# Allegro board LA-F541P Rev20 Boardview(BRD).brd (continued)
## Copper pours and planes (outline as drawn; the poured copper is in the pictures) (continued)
BST1_NVVDD on BOTTOM (solid shape): 167.04,114.91 167.04,114.82 166.94,114.72 166.71,114.72 165.57,113.58 163.56,113.58 163.51,113.63 163.51,114.21 163.53,114.22 165.37,114.22 166.14,114.99 166.96,114.99
BST1_NVVDDS on BOTTOM: 189.99,115.19 189.64,115.19 189.57,115.12 189.57,114.37 189.66,114.28 189.83,114.28 190.39,113.71 190.39,111.87 190.5,111.76 191.07,111.76 191.24,111.93 191.24,113.95
BST2_NVVDD on TOP: 171.76,113.57 170.4,113.57 169.92,114.05 169.92,114.47 170.05,114.59 170.28,114.59 170.65,114.22 171.07,114.22 171.32,114.48 171.32,114.71 171.4,114.78 172.26,114.78 172.34,114.71 172.34,114.15
BST2_NVVDD on BOTTOM: 170,114.98 169.28,114.98 169.21,114.9 169.21,114.66 170.19,113.67 170.69,113.67 170.83,113.81 170.83,114.15
BST_0.95V on BOTTOM: 108.76,60.61 108.89,60.61 109.83,59.67 110.77,59.67 111.02,59.41 111.02,58.62 110.9,58.5 109.53,58.5 108.69,59.34 108.69,60.53
BST_1.8VSP on BOTTOM (solid shape): 243.69,103.99 244.02,103.99 244.02,103.99 244.59,103.99 244.68,103.9 244.68,103.75 244.52,103.58 243.59,103.58 243.33,103.84 242.75,103.84 242.71,103.87 242.71,104.38 242.77,104.45 243.23,104.45
BST_1V on BOTTOM: 132.08,10.01 132.67,10.01 132.79,9.88 132.79,8.07 132.71,7.98 132.53,7.98 132.44,8.08 132.44,8.69 131.98,9.15 131.98,9.91
BST_1VSP on TOP (solid shape): 240.67,117.37 240.67,116.38 240.56,116.28 239.78,116.28 239.7,116.36 239.7,116.94 239.57,117.07 239.57,117.37 239.73,117.53 240.51,117.53
BST_1VSP on BOTTOM (solid shape): 240.79,117.4 240.79,116.1 240.72,116.03 240.59,116.03 240.06,116.56 239.73,116.56 239.66,116.62 239.66,116.62 239.5,116.78 239.5,117.37 239.6,117.48 240.72,117.48
BST_3V on TOP (solid shape): 343.99,25.06 343.99,24.14 343.85,24 343.85,23.24 344.11,22.99 344.11,21.85 344.04,21.78 343.96,21.78 343.88,21.86 343.88,22.84 343.26,23.46 343.26,24.99 343.35,25.08 343.97,25.08
BST_5V on TOP (solid shape): 344.1,19.78 344.1,18.54 343.85,18.29 342.9,18.29 342.9,18.29 342.71,18.29 342.52,18.1 342.52,17.34 342.39,17.21 341.63,17.21 341.5,17.34 341.5,18.23 341.95,18.67 343.72,18.67 343.89,18.84 343.89,19.78 343.93,19.81 344.07,19.81
DCIN_ISL88738 on TOP (solid shape): 54.3,14.2 54.3,12.86 54.26,12.82 53.44,12.82 53.02,13.24 52.09,13.24 51.85,13.48 51.51,13.48 51.36,13.63 50.52,13.63 50.5,13.65 50.5,13.78 50.52,13.8 51.79,13.8 52,14.01 53.06,14.01 53.34,14.3 54.21,14.3
DH1_NVVDD on BOTTOM (solid shape): 174.42,102.13 174.42,100.97 174.27,100.81 172.64,100.81 172.39,101.07 172.39,101.8 172.39,101.8 172.39,101.99 172.7,102.29 174.27,102.29
DH1_NVVDD on IN4 (solid shape): 174.68,101.93 174.68,100.89 174.52,100.74 172.75,100.74 172.34,101.14 172.34,102.03 172.53,102.22 174.38,102.22
DH1_NVVDD on BOTTOM: 166.99,115.41 165.57,115.41 164.94,114.78 164.94,114.44 165.06,114.32 165.28,114.32 166.06,115.11 166.94,115.11 167.06,115.23 167.06,115.34
DH1_NVVDD on IN4: 165.75,115.3 165.04,115.3 164.7,114.96 164.7,113.73 164.86,113.57 165.46,113.57 165.89,114 165.89,115.16
DH1_NVVDDS on BOTTOM (solid shape): 192.87,109.74 192.87,109.33 193.07,109.13 193.07,108.82 192.84,108.59 191.9,108.59 191.78,108.72 191.78,109.76 191.9,109.88 192.73,109.88
DH1_NVVDDS on IN4 (solid shape): 192.86,109.81 192.86,109.35 192.03,108.52 190.86,108.52 190.86,109.21 190.93,109.28 191.31,109.28 191.96,109.93 192.74,109.93
DH1_NVVDDS on BOTTOM: 189.41,115.21 189.24,115.21 189.18,115.15 189.18,114.1 189.33,113.95 189.33,113.69 189.36,113.66 189.36,113.16 189.49,113.03 189.99,113.03 190.25,113.29 190.25,113.62 189.69,114.18 189.55,114.18 189.44,114.29 189.44,115.18
DH1_NVVDDS on IN4: 190.03,114.23 189.49,114.23 189.33,114.06 189.33,112.17 189.49,112.02 189.99,112.02 190.2,112.22 190.2,114.07
DH2_NVVDD on BOTTOM (solid shape): 174.63,107.97 174.63,107.02 174.52,106.91 174.16,106.91 174.15,106.92 173.29,106.92 173.1,107.11 173.1,107.97 173.36,108.23 174.37,108.23
DH2_NVVDD on IN4 (solid shape): 171.84,114.5 171.84,114.02 171.68,113.85 171.33,113.85 170.23,114.95 170.23,115.16 170.41,115.34 171,115.34
DH2_NVVDD on IN4 (solid shape): 174.54,107.99 174.54,107.2 174.28,106.94 172.7,106.94 172.63,107 172.63,107.64 172.89,107.89 173.52,107.89 173.78,108.15 174.37,108.15
DH2_NVVDD on BOTTOM: 170.1,115.4 169.3,115.4 169.22,115.32 169.22,115.17 169.32,115.07 170.06,115.07 170.78,114.35 171.08,114.35 171.21,114.49 171.21,114.75 170.65,115.31 170.18,115.31
DH_1.2V on BOTTOM (solid shape): 287.29,29.78 287.29,29.68 287.24,29.64 286.18,29.64 285.37,28.83 285.18,28.83 285.05,28.96 285.05,29.38 285.51,29.85 287.22,29.85
DH_1.2V on BOTTOM (solid shape): 272.04,34.16 272.04,33.4 271.92,33.29 271.5,33.29 271.48,33.28 270.64,33.28 270.16,33.75 270.16,34.7 270.26,34.8 271.4,34.8
DH_1.2V on IN6 (solid shape): 271.27,34.74 271.27,32.45 271.15,32.32 270.32,32.32 270.07,32.58 270.07,34.74 270.26,34.93 271.08,34.93
DH_1.2V on IN6 (solid shape): 285.31,29.91 285.81,29.91 286.01,29.72 286.01,29.47 285.37,28.83 284.99,28.83 284.29,29.53 284.29,29.66 284.86,30.23 284.99,30.23
DL1_NVVDD on BOTTOM (solid shape): 168.5,99.59 168.5,99.06 168.43,98.98 167.49,98.98 166.93,98.43 166.93,97.94 166.8,97.82 166.45,97.82 166.4,97.87 166.4,98.96 166.47,99.04 166.73,99.04 167.01,99.32 167.01,99.62 167.16,99.77 168.33,99.77
DL1_NVVDD on TOP: 166.4,97.97 166.55,97.82 168.38,97.82 168.43,97.87 168.43,98.4 168.17,98.65 167.46,98.65 167.08,99.04 166.45,99.04 166.4,98.98
DL1_NVVDD on BOTTOM: 167.81,114.55 167.65,114.55 167.57,114.47 167.57,113.62 166.85,112.9 166.85,112.64 166.99,112.5 167.25,112.5 167.86,113.12 167.86,114.5
DL1_NVVDD on IN3: 167.34,113.41 166.65,112.73 166.65,111.12 168.56,109.21 168.56,106.08 167.78,105.3 167.78,99.86 167.03,99.11 167.01,99.11 166.88,98.98 166.35,98.98 166.12,98.76 166.12,97.84 166.32,97.64 166.98,97.64 168.83,99.48 168.83,104.79 169.89,105.85 169.89,111.32 167.81,113.4 167.35,113.4
DL1_NVVDDS on BOTTOM (solid shape): 190.42,110.95 191,110.95 191.17,110.77 191.17,109.95 191.05,109.83 189.95,109.83 189.77,110.01 189.77,111.03 189.87,111.13 190.25,111.13
DL1_NVVDDS on IN1 (solid shape): 191.71,111.85 191.71,111.34 191.39,111.02 191.39,110.05 191.22,109.88 190.84,109.88 190.58,110.13 190.58,111.47 191.29,112.18 191.38,112.18
DL1_NVVDDS on BOTTOM: 190.04,116.04 189.96,115.96 189.96,115.85 190.08,115.73 190.95,115.73 191.24,115.44 192.41,115.44 192.59,115.63 192.59,115.89 192.45,116.04
DL1_NVVDDS on IN1: 192.53,116.02 191.58,116.02 191.39,115.83 191.39,115.17 191.98,114.58 192.31,114.58 192.72,115 192.72,115.83
DL2_NVVDD on TOP: 177.32,119.5 176.93,119.5 176.36,118.93 174.89,118.93 174.49,118.54 174.49,117.96 174.66,117.79 177.01,117.79 177.49,118.27 177.49,119.33
DL2_NVVDD on BOTTOM: 168.58,114.57 168.45,114.57 168.38,114.5 168.38,112.95 168.93,112.39 169.13,112.39 169.32,112.59 169.32,112.92 168.67,113.58 168.67,114.49
DL2_NVVDD on BOTTOM: 181.59,119.51 181.59,119.51 181.48,119.39 180.71,119.39 180.59,119.27 180.59,118.32 180.74,118.16 181.94,118.16 182.35,118.57 182.35,119.33 182.17,119.51
DL2_NVVDD on IN3: 181.6,119.57 180.65,118.62 174.7,118.62 174.54,118.46 174.54,117.6 174.76,117.39 181.31,117.39 182.42,118.5 182.42,119.3 182.16,119.57
DL2_NVVDD on IN4: 169.19,112.44 168.86,112.44 168.01,113.29 168.01,114.41 168.14,114.54 168.76,114.54 168.89,114.4 168.89,113.41 169.3,113.01 169.3,112.55
DL2_NVVDD on IN4: 174.17,118.32 174.17,117.5 174.39,117.28 175.51,117.28 175.68,117.45 175.68,118.54 175.5,118.72 174.57,118.72
DL_1.2V on BOTTOM (solid shape): 287.57,29.1 287.57,28.24 286.83,27.5 286.26,27.5 286.16,27.59 286.16,27.91 287.41,29.16 287.51,29.16
DL_1.2V on BOTTOM (solid shape): 275.27,27.37 275.27,26.77 275.09,26.59 273.39,26.59 273.24,26.73 273.24,26.95 273.37,27.08 273.94,27.08 274.36,27.5 275.15,27.5
DL_1.2V on IN4: 286.36,26.14 285.86,26.65 285.86,27.6 286.77,28.51 287.48,28.51 288.16,27.84 288.16,27.14 287.16,26.14
DL_1.2V on IN4: 274,27.5 274,26.8 274.13,26.67 276.1,26.67 276.29,26.86 276.29,27.31 276.04,27.56 274.07,27.56
DTH_VDD12 on BOTTOM: 20.58,72.9 20.45,72.77 20.45,69.47 20.58,69.34 21.13,69.34 21.59,68.89 22.25,68.89 22.3,68.94 22.3,69.77 22.23,69.85 21.9,69.85 21.46,70.28 21.46,72.29 21.24,72.52 21.22,72.52 21.17,72.57 21.17,72.57 20.84,72.9
DTH_VDD33 on BOTTOM: 22.89,75.57 22.76,75.69 22.76,76.53 22.89,76.66 23.27,76.66 23.38,76.54 24.09,76.54 24.13,76.58 27.48,76.58 27.61,76.46 27.61,75.9 27.28,75.57
DTH_VDDA12 on BOTTOM: 19.74,76.99 21.92,76.99 22.66,76.25 22.66,73.53 22.53,73.41 22.15,73.41 21.97,73.58 21.97,75.95 21.74,76.18 21.39,76.18 21.11,75.9 19.76,75.9 19.64,76.02 19.64,76.89
DTH_VDDRX12 on BOTTOM: 24.6,75.44 27.05,75.44 27.43,75.06 27.43,68.07 27.2,67.84 25.6,67.84 25.3,68.15 25.3,69.22 24.92,69.6 24.92,70.31 24.72,70.51 24.71,70.51 24.41,70.82 24.41,74.56 24.51,74.66 24.51,75.35
DTH_VDDRX12 on IN3: 25,74.43 25,73.64 24.8,73.44 24.8,71.52 23.68,70.4 19.62,70.4 19.32,70.7 19.32,72.03 19.5,72.2 21.4,72.2 21.78,72.58 21.78,74.7 21.93,74.86 24.57,74.86
DTH_VDDTX12 on BOTTOM: 20.32,69.8 20.09,69.57 19.05,69.57 18.97,69.65 18.97,71.65 19.13,71.81 19.13,72.95 19.48,73.31 19.48,73.51 19.23,73.76 19.23,74.93 20.04,75.74 21.16,75.74 21.44,76.02 21.69,76.02 21.79,75.92 21.79,75.41 21.64,75.26 21.36,75.26 20.5,74.4 20.5,73.1 20.32,72.92
GPPJ_RCOMP on BOTTOM: 100.96,6.1 101.32,6.46 102.39,6.46 102.54,6.31 102.54,5.76 102.39,5.62 101.63,5.62 101.47,5.46 99.32,5.46 99.06,5.21 98.81,5.21 98.43,5.59 98.43,5.84 98.68,6.1
IA_SW1 on BOTTOM (solid shape): 142.37,115.68 144.77,115.68 147.54,112.9 147.54,110.55 147.39,110.55 147.39,110.54 139.81,110.54 139.66,110.69 139.66,111.66 139.69,111.69 140.81,111.69 141.11,112 141.11,115.53 141.28,115.7 142.35,115.7
IA_SW1 on TOP: 143.31,112.32 142.38,112.32 142.15,112.09 142.15,109.96 142.87,109.24 145.22,109.24 145.67,109.69 145.67,111.55 145.32,111.89 143.74,111.89
IA_SW2 on BOTTOM (solid shape): 147.49,116.18 147.49,115.09 147.8,114.77 152.26,114.77 154.13,112.9 154.63,112.9 154.8,112.73 154.8,110.37 154.76,110.33 154.69,110.4 149.29,110.4 148.96,110.73 148.96,110.75 148.21,111.49 147.91,111.79 147.91,112.85 146.58,114.17 146.58,116.1 146.74,116.26 147.41,116.26
IA_SW2 on TOP: 151.51,114.12 149.65,114.12 149.44,113.9 149.44,111.87 149.85,111.45 151.51,111.45 151.79,111.73 151.79,113.84
IA_SW3 on TOP (solid shape): 160.74,113.52 160.74,111.27 160.56,111.09 159.15,111.09 158.85,111.38 158.85,113.51 159.13,113.79 160.48,113.79
IA_SW3 on BOTTOM (solid shape): 156.79,115.56 156.79,114.44 156.97,114.25 160.5,114.25 160.78,113.97 160.78,112.9 160.79,112.9 160.79,112.6 161.01,112.38 162.04,112.38 162.08,112.34 162.08,110.02 162.06,110 156.71,110 156.52,110.2 156.52,111.4 156.01,111.92 156.01,115.61 156.01,115.61 156.73,115.61
LDO_IN on TOP: 68.98,29.15 67.9,29.15 67.59,28.84 67.59,27.76 67.81,27.54 68.33,27.54 68.69,27.9 69.23,27.9 69.93,27.2 69.93,26.61 69.3,25.98 66.98,25.98 66.7,26.26 66.15,26.26 65.92,26.03 65.01,26.03 64.3,25.32 64.3,24.6 66.65,22.25 66.66,22.25 66.91,22 67.34,22 67.98,22.64 67.98,23.03 69.22,24.27 69.22,24.49 70.75,26.03 70.75,27.37
LG1_ISL88738 on BOTTOM (solid shape): 49.02,9.32 49.02,8.89 48.57,8.43 48.57,7.6 48.41,7.44 47.47,7.44 47.35,7.57 47.35,9.27 47.55,9.48 48.87,9.48
LG_3V on TOP (solid shape): 341.95,22.54 342.11,22.54 342.89,21.76 343.3,21.76 343.41,21.65 343.41,21.56 343.36,21.5 342.37,21.5 342.09,21.78 341.69,21.78 341.44,22.04 341.44,22.42 341.56,22.54 341.95,22.54
LG_3V on TOP (solid shape): 338.6,22.81 338.6,21.84 338.47,21.71 338.03,21.71 337.68,21.36 337.68,21.05 337.16,20.52 336.43,20.52 336.34,20.61 336.34,21.42 336.43,21.51 336.46,21.53 336.98,21.53 337.3,21.86 337.3,22.83 337.31,22.83 337.38,22.89 338.51,22.89
LG_3V on IN1 (solid shape): 342.52,22.1 342.52,21.85 342.33,21.65 340.49,21.65 340.42,21.72 340.42,22.61 340.49,22.67 341.95,22.67
LG_3V on IN1 (solid shape): 338.6,22.8 338.6,21.36 338.43,21.19 338.39,20.96 337.31,20.96 337.19,21.08 337.19,22.7 337.38,22.89 338.5,22.89
LG_5V on TOP (solid shape): 334.47,19.15 334.47,18.27 334.33,18.13 333.45,18.13 333.16,17.84 331.96,17.84 331.87,17.94 331.87,19.21 332,19.34 334.28,19.34
LG_5V on TOP (solid shape): 343.4,20.08 343.4,19.92 343.36,19.88 342.66,19.88 342.25,19.47 341.37,19.47 341.28,19.56 341.28,19.91 341.44,20.07 342.43,20.07 342.46,20.09 343.38,20.09
LG_5V on IN1 (solid shape): 333.2,18.97 333.2,17.69 333.01,17.51 331.97,17.51 331.8,17.68 331.8,18.96 332.07,19.23 332.94,19.23
LG_5V on IN1 (solid shape): 342.39,19.94 342.39,19.62 342.23,19.46 341.72,19.46 341.3,19.05 340.11,19.05 340.11,19.94 340.23,20.07 342.27,20.07
LX1_ISL88738 on TOP (solid shape): 43.79,6.18 43.76,6.15 43.76,3.38 43.26,2.88 42.56,2.88 42.23,2.55 40.44,2.55 39.54,3.45 39.54,5.85 39.72,6.03 40.62,6.03 40.97,6.38 42.14,6.38 42.14,6.39 43.58,6.39
LX1_ISL88738 on TOP: 43.74,9.65 44.4,9.65 44.6,9.86 44.6,10.42 46,11.81 47.52,11.81 48.01,12.29 48.01,13.49 47.96,13.54 47.88,13.54 47.78,13.44 47.78,12.68 47.45,12.35 45.47,12.35 43.54,10.42 43.54,9.86
LX1_ISL88738 on BOTTOM: 41.8,12.28 41.8,12.84 42.17,13.21 43.12,13.21 43.39,12.94 46.12,12.94 46.6,12.94 46.62,12.92 46.62,8.65 46.55,8.59 42.87,8.59 41.82,7.54 41.82,6.43 42.28,5.97 43.05,5.97 43.44,5.59 43.44,2.3 43.05,1.92 39.71,1.92 39.69,1.89 38.36,1.89 37.53,2.72 33.61,2.72 32.84,3.48 32.84,7.63 35.12,9.91 38.86,9.91 40.51,11.56 41.07,11.56
LX1_NVVDD on TOP (solid shape): 173.76,102.39 173.76,100.66 174.04,100.38 176.38,100.38 176.61,100.15 176.61,96.92 174.88,95.19 169.18,95.19 169.08,95.29 169.08,102.36 169.18,102.46 173.69,102.46
LX1_NVVDD on BOTTOM (solid shape): 176.64,106.01 177.1,106.01 177.55,105.57 177.55,97.84 174.96,95.25 169.34,95.25 169.09,95.51 169.09,99.85 169.61,100.37 172.75,100.37 173.38,99.73 174.23,99.73 174.64,100.14 174.64,102.4 174.4,102.64 172.47,102.64 172.31,102.79 172.31,105.84 172.52,106.05 176.61,106.05
LX1_NVVDD on IN6 (solid shape): 174.7,98.81 174.7,97.2 174.48,96.97 174.16,96.97 173.92,97.22 173.92,98.93 174.08,99.09 174.42,99.09
LX1_NVVDD on BOTTOM: 167.39,114.59 166.81,114.59 164.7,112.48 164.7,111.95 164.65,111.9 164.24,111.9 164.2,111.86 164.2,111.02 164.38,110.85 165.12,110.85 165.29,111.02 165.29,112.22 165.61,112.54 166.29,112.54 167.47,113.72 167.47,114.51
LX1_NVVDD on IN6: 166.92,113.75 166.09,113.75 165.09,112.75 165.09,112.02 165.2,111.91 165.61,111.91 167.12,113.41 167.12,113.56
LX1_NVVDDS on TOP (solid shape): 191.01,102.68 191.01,101.35 190.88,101.22 189.23,101.22 189.04,101.41 189.04,102.74 189.49,103.19 190.5,103.19
LX1_NVVDDS on BOTTOM (solid shape): 191.8,108.05 192.91,108.05 193.17,107.8 193.17,104.42 191.97,103.22 191.97,103.2 191.82,103.05 191.82,98.86 191.64,98.68 188.85,98.68 188.15,99.38 188.15,102.9 187.55,103.49 187.55,103.53 187.28,103.81 185.8,103.81 185.32,104.29 185.32,108.87 185.55,109.09 190.76,109.09
LX1_NVVDDS on IN1 (solid shape): 190.68,104.93 190.68,102.82 190.58,102.72 189.61,102.72 189.54,102.79 189.54,104.73 189.84,105.03 190.58,105.03
LX1_NVVDDS on BOTTOM: 192.41,115.19 191.29,115.19 190.85,115.63 190.07,115.63 189.99,115.56 189.99,115.35 191.04,114.3 192.41,114.3 192.52,114.42 192.52,115.08
LX1_NVVDDS on IN1: 190.89,115.32 190.5,115.32 189.96,114.79 189.96,114.18 190.54,113.6 190.95,113.6 191.45,114.11 191.45,114.76
LX2_ISL88738 on TOP (solid shape): 40.83,15.84 40.83,13.34 40.43,12.93 40.43,12.11 39.75,11.43 35.69,11.43 35.43,11.69 35.43,16.36 35.97,16.89 39.78,16.89
LX2_ISL88738 on TOP: 43.18,13.01 43.94,13.01 45.01,14.07 45.57,14.07 46.15,14.66 47.25,14.66 47.32,14.58 47.32,14.43 47.3,14.4 46.43,14.4 43.97,11.94 43.13,11.94 43.08,11.99 43.08,12.9
LX2_ISL88738 on BOTTOM: 37.52,17.5 37.77,17.76 38.66,17.76 38.96,18.06 38.96,19.13 39.16,19.32 42.51,19.32 42.81,19.02 43.78,19.02 44,19.24 44.49,19.24 44.62,19.38 48.52,19.38 48.56,19.34 48.56,14.7 48.5,14.63 45.02,14.63 44.91,14.52 44.9,14.52 43.91,13.54 41.91,13.54 41.64,13.27 40.76,13.27 40.32,12.82 40.32,12.55 38.95,11.18 34.16,11.18 33.53,11.81 33.53,16.36 34.13,16.97 35.96,16.97 36.5,17.5
LX2_NVVDD on IN6 (solid shape): 175.67,109.35 175.67,108.28 175.44,108.05 173.79,108.05 173.66,108.18 173.66,109.37 173.86,109.58 175.44,109.58
LX2_NVVDD on TOP: 181.13,117.49 176.88,117.49 176.72,117.34 176.72,115.93 176.22,115.42 174.32,115.42 174.14,115.24 174.14,113.89 174.25,113.79 176.15,113.79 176.51,113.44 176.51,111.91 176.78,111.64 180.13,111.64 181.25,112.75 181.25,117.38
LX2_NVVDD on TOP: 169.4,113.06 170.04,113.06 170.19,113.21 170.19,113.36 169.78,113.77 169.78,114.5 169.91,114.63 169.91,115.24 169.83,115.31 169.08,115.31 169.07,115.32 169,115.32 168.97,115.29 168.97,113.49
LX2_NVVDD on BOTTOM: 177.72,106.6 175.11,106.6 174.88,106.83 174.88,108.18 174.63,108.43 173.25,108.43 173.15,108.54 173.15,109.22 173.41,109.48 173.41,110.03 173.15,110.29 173.15,111.8 173.48,112.13 173.75,112.13 174.46,112.84 174.46,112.94 175.34,113.82 175.34,117.19 175.77,117.62 181.29,117.62 181.58,117.33 181.58,112.36 180.82,111.6 178.76,111.6 178.13,110.97 178.13,107.01
LX2_NVVDD on BOTTOM: 168.98,114.59 168.84,114.59 168.77,114.52 168.77,113.73 169.48,113.02 170.03,113.02 170.16,113.15 170.16,113.41
LX2_NVVDD on IN6: 169.2,113.92 170.11,113.92 171.05,112.98 171.05,112.84 170.72,112.51 170.24,112.51 169.44,113.31 169.24,113.31 169.06,113.49 169.06,113.78
LX_0.95V on TOP (solid shape): 111.53,61.04 111.53,60.33 111.18,59.97 106.1,59.97 105.72,59.6 105.58,59.6 105.46,59.72 105.46,60.78 105.89,61.22 111.35,61.22
LX_0.95V on BOTTOM (solid shape): 114.36,61.93 114.36,59.77 113.12,58.52 112.93,58.52 112.75,58.7 112.75,59.28 112.47,59.56 111.48,59.56 111.11,59.93 109.82,59.93 108.97,60.78 108.97,61.22 109.12,61.37 109.93,61.37 110.69,62.13 114.16,62.13
LX_0.95V on BOTTOM: 106,60.91 106.76,60.91 106.83,60.83 106.83,60.64 105.75,59.56 105.55,59.56 105.36,59.75 105.36,59.75 105.32,59.8 105.32,60.23
LX_1.8VSP on BOTTOM (solid shape): 244.36,106.78 244.91,106.78 245.02,106.67 245.02,105.91 244.93,105.83 244.78,105.83 244.56,106.05 244.17,106.05 243.54,106.68 243.54,106.99 243.73,107.18 243.96,107.18
LX_1.8VSP on BOTTOM (solid shape): 241.91,103.46 241.91,102.85 241.96,102.79 243.4,102.79 243.55,102.95 243.55,103.24 243.71,103.4 244.59,103.4 244.83,103.65 245.41,103.65 245.47,103.59 245.47,102.82 245.45,102.81 245.45,101.16 245.16,100.86 240.08,100.86 240.06,100.89 240.06,103.58 240.29,103.81 241.56,103.81
LX_1.8VSP on IN4 (solid shape): 244.44,106.61 244.44,103.54 242.98,102.07 242.98,101.27 242.7,100.99 241.96,100.99 241.4,101.55 241.4,106.35 242.34,107.29 243.76,107.29
LX_1V on TOP: 131.01,8.73 135.84,8.73 136.11,8.45 136.11,7.86 135.88,7.62 130.96,7.62 130.71,7.88 130.71,8.43
LX_1V on BOTTOM: 134.68,7.68 135.78,7.68 136.28,8.17 136.28,8.53 136.22,8.59 135.21,8.59 134.63,8.01 134.63,7.73
LX_1V on BOTTOM: 132.08,8.79 132.08,8.29 132.51,7.87 132.51,7.29 132.43,7.21 130.92,7.21 130.69,6.99 130.69,3.42 130.69,3.41 130.69,2.12 130.56,1.99 129.42,1.99 129.28,2.13 129.28,4.59 128.6,5.28 128.6,9.25 129.27,9.93 130.28,9.93 130.31,9.89 130.31,9.18 130.58,8.92 131.95,8.92
LX_1VSP on TOP (solid shape): 234.38,116.21 234.38,114.81 234,114.43 232.09,114.43 231.84,114.68 231.84,116.27 231.97,116.4 234.19,116.4
LX_1VSP on TOP (solid shape): 243.97,116.54 243.97,116.13 243.21,115.37 241.3,115.37 241.15,115.22 238.91,115.22 238.58,114.89 237.87,114.89 237.75,115.01 237.75,115.77 238.1,116.13 240.82,116.13 241.33,116.64 243.87,116.64
LX_1VSP on BOTTOM (solid shape): 243.97,116.46 243.97,116.21 243.49,115.72 242.72,115.72 242.65,115.8 242.65,115.95 242.74,116.04 242.74,116.32 243.03,116.61 243.82,116.61
LX_1VSP on BOTTOM: 238.74,115.09 238.91,115.27 240.39,115.27 240.49,115.37 240.49,115.88 240.12,116.24 239.27,116.24 239.05,116.46 233.6,116.46 233.38,116.23 233.38,113.97 233.66,113.69 236.83,113.69 238.23,115.09
LX_3V on TOP (solid shape): 344.62,24.13 344.62,23.24 344.49,23.12 344.49,22.16 344.3,22.16 344.3,23.05 344.04,23.31 344.04,24 344.12,24.08 344.12,24.17 344.21,24.26 344.49,24.26
LX_3V on TOP (solid shape): 338.72,33.91 339.19,33.44 339.19,28.2 339.97,27.41 339.97,25.31 340.23,25.05 340.23,23.99 340,23.76 337.27,23.76 336.89,23.37 336.89,22.27 336.67,22.06 334.04,22.06 333.82,22.27 333.82,23.18 333.69,23.31 331.11,23.31 330.89,23.52 330.89,24.76 331.28,25.15 333.38,25.15 334.2,25.97 334.2,30.16 334.84,30.81 335.54,30.81 336.22,31.48 336.22,33.7 336.43,33.91 336.8,33.91
LX_3V on IN6 (solid shape): 339.6,29.17 339.6,27.76 341.45,25.91 343.07,25.91 344.73,24.26 344.73,23.24 344.46,22.98 343.72,22.98 342.38,24.31 340.25,24.31 337.82,26.74 337.82,29.17 338.16,29.51 339.26,29.51
LX_5V on TOP (solid shape): 344.49,19.69 344.49,18.8 345.06,18.23 346.77,18.23 347.28,17.72 347.28,17.21 347.16,17.08 345.12,17.08 344.74,17.46 344.74,18.16 344.62,18.29 344.43,18.29 344.3,18.42 344.3,19.69 344.36,19.75 344.43,19.75
LX_5V on IN1 (solid shape): 338.71,9.7 338.2,9.19 337.82,9.19 337.31,9.7 336.61,9.7 336.29,10.01 336.29,10.46 336.48,10.65 337.75,10.65
LX_5V on IN1 (solid shape): 348.81,17.4 348.81,16.83 348.5,16.52 348.37,16.52 348.27,16.42 347.45,17.24 346.93,17.24 346.4,17.77 346.4,18.09 346.57,18.26 346.58,18.26 346.74,18.42 347.79,18.42
LX_5V on TOP: 326.52,14.1 326.77,14.35 331.8,14.35 332.01,14.56 332.01,14.99 332.01,15 332.01,16.43 333.48,17.91 338.13,17.91 338.39,17.64 338.39,14.02 338.95,13.46 340.63,13.46 340.79,13.3 340.79,3.75 340.13,3.1 332.56,3.1 331.9,3.76 331.9,9.55 331.12,10.33 327.44,10.33 326.52,11.26
Net_269 on BOTTOM (solid shape): 222.19,30.8 214.19,30.8 214.19,38.8 222.19,38.8
Net_270 on BOTTOM (solid shape): 210.38,30.93 202.38,30.93 202.38,38.93 210.38,38.93
Net_271 on BOTTOM (solid shape): 241.69,30.43 226.69,30.43 226.69,40.43 241.69,40.43
PP_HV on TOP: 23.69,55.2 22.88,55.2 22.51,54.83 22.51,53.93 22.59,53.85 22.72,53.85 22.72,53.86 23.31,53.86 23.45,53.72 23.88,53.72 24.24,54.09 24.24,54.47 24.08,54.63 23.86,54.63 23.81,54.68 23.81,55.07
PP_HV on BOTTOM: 23.33,54.99 23.03,55.29 23.03,55.51 23.2,55.68 23.27,55.68 23.45,55.86 23.45,55.92 23.53,56.01 23.74,56.01 23.8,55.95 23.8,55.77 23.95,55.62 24.11,55.62 24.49,55.24 24.49,54.28 24.15,53.94 23.42,53.94 23.33,54.03
PWR_VGA_CORE_BOOT1 on TOP: 195.07,116.14 195.07,116.02 195.77,115.32 198.12,115.32 198.12,116.08 197.93,116.27 195.2,116.27
PWR_VGA_CORE_LGATE1 on BOTTOM (solid shape): 202.82,121.03 202.82,119.64 202.69,119.51 201.55,119.51 201.42,119.64 201.42,120.14 201.17,120.4 200.08,120.4 199.39,119.71 199.39,119.25 199.26,119.13 198.76,119.13 198.63,119.25 198.63,120.04 199.75,121.16 202.69,121.16
PWR_VGA_CORE_LGATE1 on IN3 (solid shape): 203.07,120.27 203.07,120.02 202.06,119 201.55,119 201.42,119.13 201.42,120.27 201.68,120.52 202.82,120.52
PWR_VGA_CORE_LGATE1 on TOP: 194.23,115.52 194.23,114.85 193.68,114.3 192.41,114.3 192.28,114.17 192.28,113.67 192.41,113.54 194.06,113.54 194.43,113.91 194.43,115.52
PWR_VGA_CORE_LGATE1 on IN3: 193.17,115.32 193.17,113.67 193.3,113.54 194.57,113.54 194.69,113.67 194.69,115.57 194.57,115.7 193.55,115.7
PWR_VGA_CORE_PHASE1 on TOP (solid shape): 206.84,117.23 206.84,116.06 206.78,116 204.51,116 204,115.49 203.71,115.49 203.4,115.79 203.4,117.16 203.71,117.46 206.61,117.46
PWR_VGA_CORE_PHASE1 on BOTTOM (solid shape): 204.22,118.62 204.22,114.68 204.09,114.56 199.77,114.56 199.39,114.94 199.39,115.83 199.18,116.04 195.11,116.04 194.95,116.21 194.95,118.62 195.07,118.75 204.09,118.75
PWR_VGA_CORE_PHASE1 on TOP: 194.95,114.05 194.63,114.36 194.63,115.57 194.82,115.57 195.33,115.06 198.25,115.06 198.38,115.19 198.38,115.95 198.5,116.08 199.9,116.08 200.03,115.95 200.03,114.49 199.58,114.05
PWR_VGA_CORE_UGATE1 on BOTTOM (solid shape): 200.92,113.79 200.92,112.27 200.79,112.14 200.28,112.14 200.15,112.27 200.15,113.16 199.9,113.41 198.76,113.41 198.63,113.54 198.63,113.92 198.76,114.05 200.66,114.05
PWR_VGA_CORE_UGATE1 on TOP: 195.33,116.65 195.9,116.65 196.72,117.48 196.72,117.6 197.42,118.3 198.76,118.3 198.88,118.17 198.88,117.73 198.69,117.54 197.42,117.54 196.36,116.47 195.33,116.47
PWR_VGA_CORE_UGATE1 on TOP: 200.15,113.67 200.34,113.86 200.92,113.86 201.11,113.67 201.11,112.33 200.92,112.14 200.28,112.14 200.15,112.27
RING2 on BOTTOM (solid shape): 8.9,44.95 8.9,43.87 8.98,43.79 8.98,42 8.88,41.91 8.77,41.91 8.71,41.96 8.71,43 8.67,43.05 8.67,43.69 8.65,43.7 8.65,43.73 8.42,43.96 8.42,44.38 8.37,44.43 8.37,44.91 8.51,45.05 8.8,45.05
RING2 on IN1 (solid shape): 9.31,46.32 9.31,45.28 9.05,45.02 9.02,45 8.99,44.96 8.92,44.74 8.99,44.52 8.99,44.38 8.92,44.19 8.96,43.99 8.76,43.8 8.37,43.8 8.19,43.98 8.19,44.44 8.23,44.6 8.19,44.77 8.13,44.86 8.04,44.92 7.91,45.05 7.91,45.82 7.92,45.83 7.92,46.03 8.29,46.41 9.22,46.41
RING2 on BOTTOM: 10.68,57.55 9.91,57.55 9.36,58.12 8.63,58.4 8.53,58.49 8.53,59.36 8.59,59.43 9.93,59.43 10.06,59.3 10.06,58.87 10.39,58.54 10.61,58.54 10.81,58.34 10.81,57.68
RING2 on IN1: 15.11,56.58 15.11,52.58 15.01,52.48 13.69,52.48 13.41,52.76 13.41,56.24 12.47,57.18 10.37,57.18 9.29,58.26 9.14,58.26 9.02,58.37 9.02,58.66 9.11,58.75 11.28,58.75 11.45,58.57 13.12,58.57
RING2_L on BOTTOM: 2.55,56.36 2.4,56.51 2.4,57.56 3.35,58.51 3.35,58.77 4.06,59.48 4.2,59.48 4.3,59.39 5.04,59.39 5.13,59.48 5.77,59.48 5.94,59.31 5.94,58.81 6.09,58.66 7.16,58.66 7.64,59.15 7.64,59.26 7.78,59.4 8.27,59.4 8.32,59.36 8.32,58.41 7.75,58.29 7.26,57.99 5.76,57.99 4.93,58.82 4.36,58.82 4.2,58.66 4.2,57.51 4,57.32 4,56.62 3.75,56.36
RREF on BOTTOM (solid shape): 338.38,36.25 338.38,36.07 337.17,34.86 337.17,33.74 337.15,33.72 336.59,33.72 336.59,34.88 337.49,35.78 337.49,36.22 337.57,36.3 338.33,36.3
SD_REG2 on BOTTOM (solid shape): 343.69,40.4 343.69,39.93 343.39,39.63 342.81,39.63 342.81,39.63 341.85,39.63 341.42,39.19 341.34,39.19 341.28,39.25 341.28,40.04 341.62,40.38 342.84,40.38 342.98,40.51 343.57,40.51
SLEEVE on TOP (solid shape): 9.53,45.68 9.53,44.09 9.41,43.98 9.12,43.98 9.01,44.09 9.01,44.94 8.86,45.08 8.75,45.08 8.74,45.09 8.64,45.1 8.54,45.09 8.53,45.08 6.87,45.08 6.74,45.21 6.74,45.82 6.83,45.9 9.31,45.9
SLEEVE on BOTTOM (solid shape): 9.54,44.82 9.54,44.56 9.54,44.56 9.54,44.16 9.55,44.15 9.55,43.99 9.36,43.8 9.36,42 9.28,41.92 9.18,41.92 9.12,41.98 9.12,43.82 9.02,43.92 9.02,44.8 9.1,44.88 9.48,44.88
SLEEVE on IN2 (solid shape): 10.19,46.1 10.19,45.14 10.13,45.08 10,45.08 9.92,45.09 9.84,45.08 9.77,45.08 9.71,45.02 9.56,44.73 9.71,44.44 9.71,44.18 9.41,43.88 9.04,43.88 8.94,43.97 8.96,44.01 8.99,44.19 8.93,44.37 8.92,44.38 8.92,44.48 8.94,44.5 8.94,44.55 8.95,44.56 8.96,44.89 8.7,45.09 8.66,45.1 8.66,45.99 8.9,46.24 10.05,46.24
SLEEVE on BOTTOM: 12.64,59.43 13.61,59.43 14.91,58.12 14.91,57.94 14.69,57.71 13.83,57.71 12.86,58.69 12.64,58.69 12.57,58.76 12.57,59.36
SLEEVE on IN2: 15.1,54.76 14.9,54.56 13.56,54.56 13.41,54.71 13.41,58.02 13.23,58.21 13.23,58.75 13.32,58.84 14.19,58.84 15.1,57.93
SLEEVE_L on TOP (solid shape): 3.71,46.27 3.71,46.07 4.02,45.77 4.73,45.77 5.16,46.19 6.29,46.19 6.41,46.07 6.41,45.26 6.35,45.2 3.07,45.2 2.66,45.61 2.66,46.22 2.74,46.3 3.68,46.3
SNB_0.95V on TOP (solid shape): 110.26,63.58 110.26,62.76 110.14,62.64 106.45,62.64 106.38,62.71 106.38,63.49 106.39,63.54 106.41,63.56 107.27,63.56 107.42,63.7 110.14,63.7
SNB_1.8VSP on BOTTOM (solid shape): 242.19,99.82 242.19,97.54 241.94,97.28 240.67,97.28 240.29,97.66 240.29,99.82 240.41,99.95 242.06,99.95
SNB_1V on BOTTOM (solid shape): 128.22,3.76 128.39,3.59 128.39,1.66 128.29,1.56 126.28,1.56 126.12,1.71 126.12,3.6 126.29,3.78 128.22,3.78
SNB_1VSP on TOP (solid shape): 235.97,116.33 235.97,115.89 236.22,115.63 237.36,115.63 237.49,115.51 237.49,114.68 237.36,114.56 234.95,114.56 234.76,114.75 234.76,116.4 234.82,116.46 235.84,116.46
SNUB_1.2V on BOTTOM (solid shape): 267.46,28.26 267.46,26.61 267.27,26.42 266.32,26.42 266.19,26.54 266.19,27.24 265.94,27.5 265.05,27.5 264.86,27.69 264.86,28.26 265.05,28.45 267.27,28.45
SNUB_3V on TOP (solid shape): 334.92,33.77 334.93,33.77 334.93,32.3 334.82,32.19 332.69,32.19 332.49,32.39 332.49,33.2 332.62,33.34 333.13,33.34 333.68,33.89 334.81,33.89
SNUB_5V on TOP (solid shape): 340.81,17.27 340.81,14.68 340.55,14.43 339.07,14.43 338.77,14.73 338.77,17.27 338.95,17.44 340.64,17.44
SNUB_CHG1 on TOP: 38.86,6.91 38.86,3.91 38.61,3.66 37.19,3.66 36.96,3.89 36.96,6.63 37.36,7.04 38.74,7.04
SNUB_CHG2 on TOP (solid shape): 34.3,15.32 34.3,13.24 33.81,12.75 33.02,12.75 32.58,13.18 32.58,15.34 32.71,15.47 34.15,15.47
SW_1.2V on BOTTOM (solid shape): 287.29,29.38 287.29,29.29 287.15,29.15 286.77,29.15 284.93,27.31 284.29,27.31 284.16,27.43 284.16,28.32 284.23,28.39 285.18,28.39 286.24,29.45 287.22,29.45
SW_1.2V on BOTTOM (solid shape): 269.8,34.01 269.8,33.6 270.38,33.02 272.04,33.02 272.16,32.89 272.16,30.75 272.95,29.97 272.95,26.37 272.86,26.29 268.86,26.29 268.54,26.61 268.54,28.32 266.96,29.91 266.96,33.94 267.14,34.13 269.68,34.13
SW_1.2V on IN6 (solid shape): 272.86,29.89 272.86,28.5 272.6,28.23 270.96,28.23 270.61,28.58 270.61,30.24 270.75,30.38 272.37,30.38
SW_1.2V on IN6 (solid shape): 286.45,28.95 286.45,28.61 285.59,27.75 283.5,27.75 283.4,27.86 283.4,28.72 283.54,28.86 284.56,28.86 284.77,28.66 285.46,28.66 285.93,29.13 286.28,29.13
TBT_SVR_IND on BOTTOM (solid shape): 23.81,50.23 23.81,48.13 23.6,47.92 23.6,46.47 23.59,46.46 23.59,46.1 23.44,45.94 23.44,44.8 23.37,44.74 23.24,44.74 23.11,44.6 23.11,44.45 23.03,44.37 22.82,44.37 22.72,44.48 22.72,45.51 22.86,45.65 22.86,45.76 22.86,46.56 22.77,46.65 22.77,50.27 22.92,50.42 23.62,50.42
TBTA_CC1 on TOP (solid shape): 10.07,67.55 10.07,66.82 9.95,66.69 8.96,66.69 8.75,66.91 7.38,66.91 7.31,66.98 7.31,67.14 7.39,67.22 8.91,67.22 9.3,67.61 10.01,67.61
TBTA_CC1 on BOTTOM: 26.16,62.73 25.85,62.73 25.63,62.51 25.63,62.28 24.69,61.34 24.69,60.78 24.46,60.55 24.46,59.78 24.5,59.74 24.74,59.74 24.78,59.78 24.78,60.36 25.15,60.73 25.15,61.24 26.28,62.37 26.28,62.61
TBTA_CC2 on BOTTOM: 25.69,61.28 25.36,61.28 25.25,61.16 25.25,60.71 24.85,60.31 24.85,59.83 24.94,59.74 25.17,59.74 25.26,59.83 25.26,60.01 25.81,60.55 25.81,61.16
UG1_ISL88738 on TOP (solid shape): 43.89,2.46 43.89,1.27 43.83,1.22 42.38,1.22 42.31,1.28 42.31,2.33 42.58,2.59 43.75,2.59
UG1_ISL88738 on BOTTOM (solid shape): 43.94,7.53 43.94,6.48 43.69,6.22 42.28,6.22 42.12,6.38 42.12,7.28 42.71,7.87 43.6,7.87
UG1_ISL88738 on IN3: 42.8,8.38 43.94,8.38 44.45,7.88 44.45,1.65 43.94,1.14 42.67,1.14 42.42,1.4 42.42,8
UG_3V on TOP (solid shape): 343.7,22.76 343.7,21.83 343.66,21.79 343.55,21.79 343.45,21.89 343.45,22.51 343.35,22.61 343.09,22.61 342.46,23.24 342.46,23.43 342.58,23.56 342.9,23.56
UG_3V on IN1 (solid shape): 331.88,25.54 331.88,24.58 331.75,24.46 329.85,24.46 329.78,24.52 329.78,25.73 329.97,25.92 331.5,25.92
UG_3V on IN1 (solid shape): 343.47,23.75 343.47,22.73 343.35,22.61 342.77,22.61 341.76,23.62 341.76,23.94 342.33,24.51 342.71,24.51
UG_3V on TOP: 329.88,25.85 330.71,25.85 330.82,25.74 330.82,23.55 330.75,23.48 329.98,23.48 329.83,23.63 329.83,25.79
UG_5V on TOP (solid shape): 331.76,13.82 331.76,13.17 331.75,13.16 331.75,13.07 331.54,12.86 331.22,12.86 331.06,13.02 330.59,13.02 330.3,13.31 330.3,13.8 330.46,13.95 331.63,13.95
UG_5V on TOP (solid shape): 343.71,19.78 343.71,18.87 343.63,18.8 342.33,18.8 342.27,18.86 342.27,19.18 342.46,19.37 343.41,19.37 343.47,19.43 343.47,19.5 343.47,19.5 343.47,19.75 343.53,19.81 343.68,19.81
UG_5V on IN1 (solid shape): 332.18,14.04 332.18,13.34 331.54,12.7 330.76,12.7 330.6,12.85 330.6,13.73 331.24,14.37 331.85,14.37
UG_5V on IN1 (solid shape): 344.3,18.42 344.3,17.65 343.98,17.34 343.73,17.34 342.71,18.35 342.52,18.35 342.2,18.67 342.2,19.11 342.39,19.31 343.41,19.31
VCORE_B+ on TOP: 137.07,117.81 137.34,118.09 137.34,119.86 137.54,120.07 138.59,120.07 138.82,119.84 138.82,117.99 138.53,117.71 138.53,114.35 138.08,113.89 137.25,113.89 136.39,113.03 134.21,113.03 133.9,112.72 133.9,112.34 133.73,112.17 126.9,112.17 126.72,112.35 126.72,117.56 126.98,117.81
VCORE_B+ on TOP: 155,120.22 155,120.21 155.26,119.95 155.26,117.53 155,117.27 150.6,117.27 150.47,117.4 150.47,119.43 150.67,119.64 151.26,119.64 151.84,120.22
VCORE_B+ on TOP: 159.84,118.21 159.63,118 158.94,118 158.78,117.85 158.78,117.13 159.12,116.8 160.75,116.8 160.96,117.01 162.99,117.01 163.5,117.52 163.5,119.29 163.25,119.54 162.72,119.54 161.92,120.34 161.92,121.06 161.8,121.17 159.98,121.17 159.84,121.04
VCORE_B+ on BOTTOM: 162.8,116.78 158.85,116.78 158.7,116.93 158.7,117.91 158.88,118.09 160,118.09 160.23,118.32 160.23,118.7 160.24,118.71 160.24,120.87 160.35,120.98 162.74,120.98 163.21,120.51 163.21,119.42 163.5,119.13 163.5,117.48
VCORE_B+ on BOTTOM: 126.67,116.66 133.58,116.66 133.99,117.07 133.99,119.91 133.96,119.94 133.96,120.32 134.46,120.82 137.43,120.82 137.89,120.37 138.59,120.37 138.82,120.14 138.82,118.05 138.59,117.81 138.59,117.09 138.58,117.08 138.58,113.8 138.48,113.7 137.34,113.7 137.28,113.76 137.28,115.03 137.03,115.28 136.44,115.28 136.33,115.39 136.33,115.94 136.02,116.26 135.13,116.26 134.29,115.42 134.29,114.63 133.91,114.25 133.91,110.93 133.22,110.24 132.46,110.24 130.43,108.2 130.43,107.45 130.19,107.21 126.42,107.21 126.18,107.45 126.18,111.06 125.32,111.91 125.32,115.32
VCORE_B+ on BOTTOM: 154.2,117.26 154.34,117.4 154.34,118.29 154.53,118.49 155.29,118.49 155.56,118.76 155.56,120.31 155.25,120.62 155.25,120.63 153.12,120.63 152.17,119.68 151.2,119.68 151.12,119.59 151.12,118.91 150.98,118.77 149.74,118.77 149.56,118.59 149.56,117.44 149.73,117.26
VCORE_B+ on IN4: 127.09,116.47 127.41,116.79 132.76,116.79 136.65,120.68 162,120.68 163.73,118.95 163.73,112.37 162.61,111.25 128.06,111.25 127.09,112.22 ; 1 cut-out
N16399089 on TOP: 55.6,14.35 56.01,14.76 56.01,15.71 56.93,16.64 56.93,17.07 56.94,17.07 57.61,17.07 57.64,17.05 57.64,16.74 57.72,16.66 60.25,16.66 60.4,16.51 60.4,16.35 60.39,16.34 60.39,15.09 60.21,14.92 57.23,14.92 57.23,14.92 57.02,14.92 56.64,14.54 56.64,12.96 56.52,12.83 55.12,12.83 55.12,14.23 55.25,14.35
N17034092 on TOP (solid shape): 341.2,22.66 341.2,22.08 341.65,21.64 342.04,21.64 342.34,21.34 343.35,21.34 343.41,21.28 343.41,21.14 343.37,21.1 342.31,21.1 342.15,21.26 341.02,21.26 340.92,21.16 340.35,21.16 340.3,21.2 340.3,22.72 340.33,22.75 341.11,22.75
N19473637 on TOP (solid shape): 181.87,18.29 181.87,17.02 182.5,16.38 183.01,16.38 184.09,15.3 184.09,14.69 183.82,14.43 182.65,14.43 182.13,13.91 180.95,13.91 180.87,13.98 180.87,15.05 180.46,15.47 180.46,16.92 180.82,17.29 180.82,18.26 180.89,18.33 181.83,18.33
N32074224 on TOP (solid shape): 207.52,120.91 207.52,119.38 207.01,118.87 204.85,118.87 204.73,119 204.73,120.65 205.23,121.16 207.27,121.16
N48708347 on BOTTOM (solid shape): 283.53,29.59 283.53,27.44 283.42,27.33 282.93,27.33 282.7,27.56 282.7,29.53 282.83,29.66 283.47,29.66
N55155823 on TOP: 44.45,35.18 44.45,33.91 44.2,33.66 44.07,33.66 43.03,34.7 42.09,34.7 41.91,34.88 40.18,34.88 40.08,34.98 40.08,35.51 40.18,35.61 44.02,35.61
N110703687 on TOP (solid shape): 176.74,103.22 176.74,101.5 176.45,101.22 174.71,101.22 174.54,101.39 174.54,103.22 174.77,103.45 176.51,103.45
N116496514 on TOP (solid shape): 175.85,117.48 175.85,116.49 175.76,116.4 173,116.4 172.81,116.59 172.81,117.34 173.03,117.55 175.77,117.55
N119942216 on BOTTOM: 17.22,85.68 16.96,85.94 16.96,89.59 17.13,89.76 18.2,89.76 18.23,89.74 24.07,89.74 24.67,90.34 26.19,90.34 26.29,90.24 26.29,89.59 26.54,89.35 26.54,85.83 26.39,85.68
N120970730 on TOP: 145.52,114.66 143.77,114.66 143.62,114.5 143.62,112.31 143.76,112.17 145.47,112.17 145.7,112.41 145.7,114.48
N120971346 on TOP: 148.08,114.49 146.78,114.49 146.54,114.26 146.54,111.75 146.82,111.47 147.85,111.47 148.2,111.82 148.2,114.37
N120971480 on TOP (solid shape): 158.01,114.22 158.01,111.31 157.79,111.09 156.59,111.09 156.47,111.21 156.47,114.22 156.57,114.33 157.91,114.33
N122528028 on TOP (solid shape): 237.99,44.3 238.76,44.3 238.84,44.22 238.84,42.22 238.64,42.03 236.64,42.03 236.43,42.24 236.43,43.19 236.3,43.32 235.71,43.32 235.53,43.49 235.53,44.27 235.72,44.46 237.83,44.46
N123983992 on TOP (solid shape): 114.12,70.13 114.12,68.09 113.79,67.76 111.34,67.76 110.87,68.23 110.87,68.92 110.87,68.92 110.87,70.23 111.19,70.55 113.7,70.55
N123983992 on BOTTOM (solid shape): 110.3,74.87 113.03,74.87 113.04,74.86 114.24,74.86 114.92,74.18 114.92,71.87 114.53,71.48 113.44,71.48 113.35,71.39 113.35,70.35 113.39,70.31 114.56,70.31 114.91,69.95 114.91,67.46 114.78,67.34 111.74,67.34 110.49,68.58 110.49,72.14 109.67,72.96 109.16,72.96 108.97,73.15 108.97,75.19 109.03,75.25 109.92,75.25
N123984012 on BOTTOM (solid shape): 108.91,99.11 108.91,99.11 108.91,98.99 108.93,98.97 109.64,98.97 109.66,98.99 109.66,99.49 110.11,99.49 110.11,98.97 110.12,98.96 110.83,98.96 110.83,98.15 110.57,97.88 108.76,97.88 108.14,97.26 108.14,96.03 108.13,96.01 108.13,92.66 108.05,92.58 107.62,92.58 107.49,92.71 107.49,93.17 107.39,93.27 106.55,93.27 106.35,93.47 106.35,93.83 106.15,94.03 105.24,94.03 104.91,94.37 104.91,95.48 104.79,95.6 104.79,96.99 104.92,97.13 106.08,97.13 106.57,97.61 106.57,97.85 107.68,98.97 108.44,98.97 108.46,98.99 108.46,99.49 108.91,99.49
N123984012 on TOP: 105.19,97.1 105.19,94.46 105.5,94.15 107.77,94.15 108.03,94.41 108.03,96.87 108.05,96.88 108.05,97.5 108.23,97.68 108.23,98.31 108.1,98.43 106.52,98.43
N123984061 on TOP (solid shape): 113.82,97.27 113.82,96.46 113.36,96 112.82,96 112.59,96.23 112.59,97.23 112.73,97.37 113.72,97.37
N123984061 on BOTTOM (solid shape): 113.3,97.14 113.3,96.44 113.4,96.34 113.86,96.34 113.98,96.22 113.98,95.95 113.84,95.81 112.93,95.81 112.86,95.84 112.79,95.85 112.6,96.04 112.6,97.14 112.73,97.27 113.17,97.27
N123984061 on BOTTOM (solid shape): 109.46,95.21 109.46,91.89 109.51,91.85 109.51,89.66 108.6,89.66 108.59,89.65 108.59,88.89 108.6,88.88 109.5,88.88 109.5,87.28 109.21,87 104.78,87 104.63,87.15 104.63,88.5 104.63,88.5 104.63,88.8 104.73,88.9 106.8,88.9 107.06,89.16 107.06,90.93 107.7,91.57 107.71,91.57 108.4,92.26 108.4,94.82 108.41,94.82 108.41,95.21 108.44,95.25 109.43,95.25
N123984061 on IN6 (solid shape): 113.54,97.16 113.54,96.27 113.35,96.08 112.79,96.08 112.59,96.28 112.59,96.57 112.31,96.85 112.31,97.4 112.58,97.67 113.02,97.67
N123984061 on IN6 (solid shape): 109.48,92.65 109.48,91.44 109.35,91.31 108.21,91.31 108.14,91.38 108.14,92.14 108.52,92.52 108.52,92.71 108.65,92.84 109.28,92.84
N123984063 on BOTTOM (solid shape): 107.32,92.99 107.32,91.62 107.16,91.47 106.5,91.47 106.33,91.64 106.33,92.94 106.5,93.12 107.19,93.12
N123984063 on BOTTOM (solid shape): 117.41,96.39 117.41,95.76 117.39,95.73 117.32,95.72 117.26,95.7 116.81,95.7 116.8,95.7 116.37,95.7 116.27,95.81 115.38,95.81 115.3,95.89 115.3,96.25 115.51,96.46 117.35,96.46
N123984063 on IN6 (solid shape): 107.42,91.9 107.42,90.73 107.21,90.53 106.4,90.53 106.27,90.65 106.27,91.95 106.38,92.05 107.27,92.05
N123984063 on IN6 (solid shape): 117.41,96.39 117.41,95.76 117.35,95.7 116.4,95.7 116.21,95.51 116.21,94.74 116.02,94.55 115.7,94.55 115.41,94.84 115.41,96.11 115.83,96.52 117.29,96.52
N123984161 on BOTTOM (solid shape): 106.16,92.32 106.16,91.57 106.49,91.24 106.49,90.42 106.36,90.29 104.75,90.29 104.65,90.39 104.65,91.89 104.65,91.89 104.65,92.19 104.87,92.41 106.07,92.41
N123984351 on BOTTOM: 113.02,94.47 113.15,94.6 113.84,94.6 113.93,94.52 113.93,94.34 113.54,93.96 113.54,93.21 112.25,91.92 109.89,91.92 109.68,92.13 109.68,92.97 109.81,93.09 111.62,93.09 111.63,93.1 112.67,93.1 113.09,93.52 113.09,94.08 113.02,94.15
N123984423 on TOP (solid shape): 112.97,74.04 112.97,72.2 112.65,71.88 111.32,71.88 111.06,72.14 111.06,74.11 111.32,74.36 112.65,74.36
N123984459 on TOP (solid shape): 112.59,79.63 112.59,77.73 112.33,77.47 111.09,77.47 110.62,77.95 110.62,79.63 110.75,79.76 112.46,79.76
N123984461 on TOP (solid shape): 115.55,82.3 115.55,80.82 115.11,80.39 110.86,80.39 110.59,80.66 110.59,82.47 111.95,83.82 114.02,83.82
N123984461 on BOTTOM (solid shape): 115.83,84.51 115.83,83.82 115.65,83.64 114.38,83.64 114.25,83.52 114.25,82.65 114.51,82.4 115.65,82.4 115.83,82.22 115.83,80.32 115.65,80.14 110.94,80.14 110.41,80.67 109.95,80.67 109.7,80.92 109.7,83.05 109.72,83.07 110.59,83.07 111.06,83.55 111.06,84.33 111.32,84.58 111.76,84.58 111.89,84.71 115.62,84.71
N128723349 on TOP (solid shape): 191.03,105.07 191.03,104.08 191.01,104.07 189.47,104.07 189.23,103.82 188.28,103.82 188.09,104.01 188.09,104.71 188.28,104.9 188.98,104.9 189.17,105.1 191,105.1
N128725563 on BOTTOM: 163.45,113.01 164.05,113.01 164.06,113.01 164.15,113.01 164.16,113 164.29,113 164.42,112.88 164.42,112.14 164.37,112.09 164.18,112.09 164.06,111.97 164.06,110.92 164.22,110.77 165.11,110.77 165.32,110.55 165.32,109.58 165.32,109.58 165.32,109.46 165.28,109.43 163.98,109.43 163.88,109.52 163.88,110.22 163.6,110.5 163.6,110.51 163.37,110.74 163.37,112.89 163.35,112.91
N128725569 on TOP: 172.07,116.66 172.42,116.32 172.42,115.34 172.24,115.16 171.41,115.16 170.83,115.74 169.81,115.74 169.6,115.95 169.04,115.95 168.96,116.03 168.96,116.75 169.06,116.86 169.07,116.85 169.75,116.85 170.16,116.45 170.83,116.45 171.04,116.66
N128726031 on BOTTOM: 165.51,111.13 165.43,111.2 165.43,112.11 165.65,112.33 167.28,112.33 168.01,113.06 168.01,114.52 168.06,114.57 168.19,114.57 168.24,114.52 168.24,112.55 167.66,111.97 167.66,111.51 167.28,111.13
N128727405 on BOTTOM: 192.46,114.06 191.6,114.06 191.5,113.96 191.5,111.9 191.64,111.76 192.41,111.76 192.52,111.88 192.52,114
N128727995 on BOTTOM: 191.28,116.57 191.2,116.5 191.01,116.5 190.94,116.42 190.06,116.42 190,116.36 190,116.21 190.05,116.17 190.92,116.17 190.92,116.16 191.98,116.16 192.09,116.27 192.09,116.9 192.41,117.22 193.04,117.22 194.18,118.37 194.18,119.76 194.06,119.89 193.42,119.89 193.17,119.64 193.17,118.62 192.79,118.24 191.77,118.24 191.28,117.74
N128861659 on BOTTOM (solid shape): 105.72,83.39 105.72,82.74 105.67,82.69 105.03,82.69 104.91,82.81 104.91,83.17 104.65,83.43 104.65,83.44 104.4,83.69 103.87,83.69 103.82,83.75 103.82,84.27 103.87,84.33 104.78,84.33
N128862470 on BOTTOM (solid shape): 105.08,77.13 105.08,76.39 104.97,76.27 104.97,74.92 104.88,74.83 104.27,74.83 104.13,74.98 104.13,75.28 104.37,75.53 104.37,76.93 104.6,77.17 105.04,77.17
N128958713 on TOP (solid shape): 230.48,117.6 230.48,115.55 230.19,115.25 227.01,115.25 226.88,115.39 226.88,117.59 227.09,117.81 230.28,117.81
N128958713 on BOTTOM (solid shape): 232.41,117.86 232.41,113.92 232.09,113.6 228.04,113.6 227.22,114.43 225.81,114.43 225.49,114.75 225.49,117.69 225.93,118.14 232.13,118.14
N135673289 on BOTTOM (solid shape): 110.95,64.85 110.95,62.79 110.16,62 109.14,62 109.04,62.1 109.04,62.66 109.58,63.2 109.58,64.9 109.7,65.03 110.77,65.03
N135676155 on BOTTOM (solid shape): 240.54,114.56 240.54,114.05 239.52,113.03 238.33,113.03 238.23,113.13 238.23,113.64 238.41,113.82 238.94,113.82 239.5,114.38 239.5,114.53 239.65,114.68 240.41,114.68
N135689304 on BOTTOM (solid shape): 246.82,103.6 246.82,102.26 247.12,101.96 247.12,101.3 247.02,101.19 246.58,101.19 246.48,101.3 246.48,101.98 246.18,102.29 246.18,102.31 246.08,102.41 246.08,103.59 246.17,103.69 246.73,103.69
N135767755 on BOTTOM: 16.56,30.21 16.77,30 16.77,29.22 16.42,28.88 16.42,28.1 16.38,28.07 16.05,28.07 15.95,28.17 15.95,28.87 15.8,29.02 15.8,31.74 15.94,31.88 16.48,31.88 16.56,31.81
N135770638 on BOTTOM: 54.88,21.51 55.86,21.51 56.27,21.1 56.27,20.79 56.41,20.65 57.07,20.65 57.19,20.54 57.19,20.25 57.03,20.1 56.55,20.1 56.35,19.91 56.35,19.12 56.28,19.05 55.77,19.05 55.64,19.18 55.64,20.66 55.5,20.79 54.88,20.79 54.83,20.84 54.83,21.45
N135770664 on BOTTOM (solid shape): 57.38,14.06 58.01,14.06 58.12,13.96 58.12,13.69 58.03,13.6 57.34,13.6 57.18,13.44 57.18,12.85 57.15,12.81 56.57,12.81 56.51,12.88 56.51,14.29 56.58,14.36 57.09,14.36
N135770666 on BOTTOM (solid shape): 57.8,16.83 57.8,16.47 57.67,16.34 57.1,16.34 56.87,16.11 56.87,15.55 56.78,15.46 56.19,15.46 56.01,15.64 56.01,15.99 56.01,15.99 56.01,16.72 56.06,16.77 56.93,16.77 57.03,16.87 57.76,16.87
N135772460 on BOTTOM (solid shape): 54.93,16.63 54.93,15.49 54.86,15.43 54.32,15.43 54.15,15.26 54.15,14.63 54.03,14.5 53.32,14.5 53.19,14.63 53.19,15.2 53.27,15.28 53.27,15.37 53.28,15.37 53.94,16.03 53.94,16.53 54.17,16.76 54.79,16.76
N140286428 on TOP: 75.97,28.04 75.46,28.04 75.09,27.67 75.09,27.27 75.68,26.68 75.95,26.68 77.36,28.09 77.36,28.29 78.45,29.38 79.03,29.38 79.35,29.7 79.35,29.97 78.79,30.52 77.66,30.52 77.41,30.27 77.41,29.97 77.37,29.93 77.28,29.93 76.63,29.28 76.63,28.48 76.08,27.93
N140286576 on TOP: 69.4,30.02 69.4,29.29 69.66,29.03 71.06,29.03 71.24,29.21 71.86,29.21 72.8,30.15 73.47,30.15 73.78,30.46 73.78,30.84 73.29,31.33 70.72,31.33
N140286584 on TOP: 75.24,32.77 74.49,32.77 74,32.28 74,31.91 74.12,31.79 74.12,31.44 73.77,31.09 73.77,30.89 74.68,29.98 74.68,29.17 74.25,28.74 74.25,28.22 74.53,27.94 74.87,27.94 76.24,29.31 76.62,29.31 77.3,29.99 77.3,30.71
N140286634 on TOP: 72.09,31.95 73.23,31.95 73.34,31.84 73.34,31.41 73.54,31.21 73.7,31.21 73.9,31.41 73.88,31.43 73.88,32.58 74.1,32.79 74.1,33.53 73.13,34.49 72.92,34.49 71.51,33.08 71.51,32.54

Small or netless copper shapes (teardrops, artwork), in the pictures only: 73 on TOP, 41 on BOTTOM, 1 on IN1, 1 on IN5, 1 on IN6

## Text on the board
Ref Des/Silkscreen Bottom: A | B | FAN_L | C | KB | TP | HDD | FPR | FAN_R | TS | H48 | SUPPORT | DDR4 | DIMM-A | ONLY | DIMM-B | S2 | S4
User.Comments: Issued | PROJECT | BOARD NO. | LAYER NO. | DRAW BY | Security level | Decipherment date | COMPAL ELECTRONICS. INC. | Date | LA-C361P | LA-F541P | Confidential | COMP.SIDE | 2016-01-22 | 2015-01-22 | 2019-03-28 | 2018-03-28 | crazy | AAM00 | DAM00 | Win | REV:0.3(X02)
Ref Des/Silkscreen Top: H37 | H38 | S1 | SH1 | S3
IN5: IN5
IN6: IN6
DIMENSION: AGND | GND | +DC_IN | +SDC_IN | +3VALW | +1V_MPHY | +5VS | +VCCGT | +3VS | B+ | +VCC_CORE | +1.2V_DDR | +GPU_CORE | +1.35VSDGPU | +5V_CHGUSB_1
BODY_CENTER: L7 | L8 | L9 | L10 | L11 | L12 | GND3 | IN5 | IN6 | IN4 | VCC
User.42: trace Width | Width/space | 8.7mil | 5.5mil | 3.9mil | 3.6mil | 4.2 / 3.8 | 3.9 / 3.6 | 6 / 7 | 5.5 / 6.5 | 5.5 / 7.5 | 3.8 / 3.5 | 3.3 / 6.7 | 3.5 / 6.5 | 4 / 6.5 | L8/L11 | L2/L5 | L5/L8 | L2 | L11 | 4.8mil | 4.6mil | 3.1mil | 3.8 / 3 | 3.1 / 3 | 3.2 / 3.3 | L8/L10 | L9/L11 | L2/L4 | L3/L5 | L5/L7 | L6/L8 | MB_1_2mm-12L(PP1086)_WithOutC_141014.pdf | L1-TOP | L2-GND1 | L3-IN1 | L4-IN2 | L5-GND2 | L6-IN3 | L7-IN4 | L8-VCC | L9-IN5 | L10-IN6 | L11-GND3 | L12-BOT | LAYER | NAME | STACKUP: 12 LAYER | (40ohm) | 39 ohm | 50 ohm | THICKNESS=1.2mm | 85 ohm | se 48 | 88 ohm | se 50 | 90 ohm | 100 ohm | Ref | 40 ohm | 80 ohm | se 45
User.43: FIGURE | SIZE | 7.0 | 8.0 | 16.0 | 20.0 | 26.0 | 30.0 | 33.0 | 36.0 | 91.0 | 98.0 | 110.0 | 126.0 | 154.0 | 161.0 | 35.0 | 40.0 | 43.0 | 63.0 | 83.0 | 236.0 | 43.0x24.0 | 47.0x22.0 | 47.0x24.0 | 63.0x24.0 | 67.0x39.0 | 75.0x24.0 | 37.0x30.0 | 98.0x83.0 | 114.0x83.0 | DRILL CHART: TOP to BOTTOM | ALL UNITS ARE IN MILS | TOLERANCE | +3.0/-3.0 | +2.0/-2.0 | PLATED | NON-PLATED | QTY | 42 | 9642 | 12 | 19 | 2 | 18 | 4 | 5 | 1 | 6 | 8
